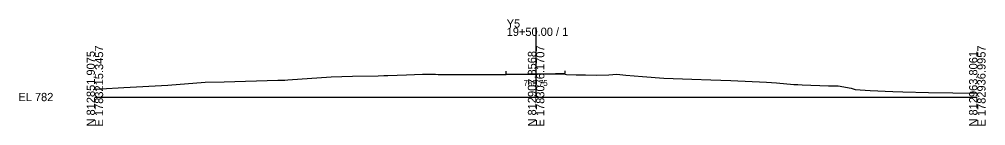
# Model space of a CAD drawing. Extents: x -26 to 1603, y -10 to 6526.
# Drawn here: x 1274.3 to 1602.8, y 6490.3 to 6526.3 of the extents above; entities that cross this region are included whole.
import ezdxf

# ---------------------------------------------------------------- set-up
doc = ezdxf.new("R2010")
doc.units = 0
for name, color, linetype in [('Exist Cross Section Cell', 7, 'Continuous'), ('Exist XS Center Line Elevation Label', 7, 'Continuous'), ('Exist XS Ground Line', 7, 'Continuous'), ('Prop XS EOT Tick Mark', 7, 'Continuous'), ('Prop XS Finish Grade Pavement', 7, 'Continuous')]:
    doc.layers.add(name, color=color, linetype=linetype)

msp = doc.modelspace()

# ---------------------------------------------------------------- linework, layer by layer
at = {"layer": 'Exist Cross Section Cell'}
for p, q in [((1450, 6500), (1450, 6523.52)), ((1300, 6500), (1450, 6500)), ((1450, 6500), (1600, 6500))]:
    msp.add_line(p, q, dxfattribs=at)
at = {"layer": 'Exist XS Ground Line'}
for p, q in [((1324.78, 6504.07), (1337.47, 6505.06)), ((1337.47, 6505.06), (1343.95, 6505.1)), ((1343.95, 6505.1), (1362.18, 6505.66)), ((1362.18, 6505.66), (1364.61, 6505.75)), ((1364.61, 6505.75), (1365.54, 6505.8)), ((1365.54, 6505.8), (1380.29, 6506.89)), ((1380.29, 6506.89), (1387.58, 6507.1)), ((1387.58, 6507.1), (1396.35, 6507.15)), ((1396.35, 6507.15), (1398.27, 6507.24)), ((1398.27, 6507.24), (1399.56, 6507.3)), ((1399.56, 6507.3), (1405.97, 6507.54)), ((1405.97, 6507.54), (1411.33, 6507.72)), ((1411.33, 6507.72), (1415.8, 6507.7)), ((1415.8, 6507.7), (1416.7, 6507.6)), ((1416.7, 6507.6), (1419.29, 6507.62)), ((1419.29, 6507.62), (1429.24, 6507.6)), ((1429.24, 6507.6), (1438.31, 6507.62)), ((1438.31, 6507.62), (1439.83, 6507.6)), ((1439.83, 6507.6), (1447.09, 6507.74)), ((1447.09, 6507.74), (1449.82, 6507.75)), ((1449.82, 6507.75), (1456.58, 6507.84)), ((1456.58, 6507.84), (1459.89, 6507.8)), ((1459.89, 6507.8), (1460.37, 6507.63)), ((1460.37, 6507.63), (1463.61, 6507.51)), ((1463.61, 6507.51), (1466.75, 6507.52)), ((1466.75, 6507.52), (1470.4, 6507.42)), ((1470.4, 6507.42), (1474.7, 6507.55)), ((1474.7, 6507.55), (1477.43, 6507.76)), ((1477.43, 6507.76), (1480.56, 6507.4)), ((1480.56, 6507.4), (1486.17, 6506.92)), ((1486.17, 6506.92), (1493.43, 6506.39)), ((1493.43, 6506.39), (1502.91, 6506.04)), ((1502.91, 6506.04), (1509.39, 6505.78)), ((1509.39, 6505.78), (1516.2, 6505.59)), ((1516.2, 6505.59), (1528.33, 6504.99)), ((1528.33, 6504.99), (1531.69, 6504.82)), ((1300, 6502.65), (1307.87, 6503.13)), ((1307.87, 6503.13), (1309.82, 6503.21)), ((1309.82, 6503.21), (1324.78, 6504.07)), ((1531.69, 6504.82), (1537.64, 6504.28)), ((1537.64, 6504.28), (1539.01, 6504.24)), ((1539.01, 6504.24), (1540.43, 6504.1)), ((1540.43, 6504.1), (1549.43, 6503.75)), ((1549.43, 6503.75), (1552.68, 6503.74)), ((1552.68, 6503.74), (1557.07, 6502.95)), ((1557.07, 6502.95), (1558.5, 6502.59)), ((1558.5, 6502.59), (1563.58, 6502.23)), ((1563.58, 6502.23), (1571.31, 6501.84)), ((1571.31, 6501.84), (1574.7, 6501.78)), ((1574.7, 6501.78), (1583.39, 6501.58)), ((1583.39, 6501.58), (1600, 6501.27))]:
    msp.add_line(p, q, dxfattribs=at)
at = {"layer": 'Prop XS EOT Tick Mark'}
for p, q in [((1439.83, 6507.72), (1439.83, 6508.72)), ((1459.89, 6507.92), (1459.89, 6508.92))]:
    msp.add_line(p, q, dxfattribs=at)
at = {"layer": 'Prop XS Finish Grade Pavement'}
for p, q in [((1439.83, 6507.72), (1447.09, 6507.87)), ((1447.09, 6507.87), (1449.82, 6507.88)), ((1449.82, 6507.88), (1456.58, 6507.96)), ((1456.58, 6507.96), (1459.89, 6507.92))]:
    msp.add_line(p, q, dxfattribs=at)

# ---------------------------------------------------------------- texts
at = {"layer": 'Exist Cross Section Cell'}
for s, p in [('Y5', (1440, 6523.52)), ('19+50.00 / 1', (1440, 6520.72)), ('EL 782', (1274, 6498.6))]:
    msp.add_text(s, height=2.8, dxfattribs=at).set_placement(p)
for s, p in [('N 812851.9075', (1300, 6490)), ('E 1783215.3457', (1302.8, 6490)), ('N 812907.8568', (1450, 6490)), ('E 1783076.1707', (1452.8, 6490)), ('N 812963.8061', (1600, 6490)), ('E 1782936.9957', (1602.8, 6490))]:
    msp.add_text(s, height=2.8, rotation=90, dxfattribs=at).set_placement(p)
at = {"layer": 'Exist XS Center Line Elevation Label'}
msp.add_text('789.75', height=2, dxfattribs=at).set_placement((1445.74, 6503.75))

doc.saveas('drawing.dxf')
